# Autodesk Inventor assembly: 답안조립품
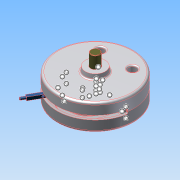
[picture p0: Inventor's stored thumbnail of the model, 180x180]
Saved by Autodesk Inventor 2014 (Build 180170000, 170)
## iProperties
Created: 2015-06
Part Number: 답안조립품
Document SubType Name: Assembly
Designer: Administrator
Author: Administrator
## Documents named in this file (10)
- C:\Documents and Settings\Administrator\바탕 화면\450631V1026\답안조립품.iam
- C:\Documents and Settings\Administrator\바탕 화면\450631V1026\1-본체.ipt
- C:\Documents and Settings\Administrator\바탕 화면\450631V1026\베어링62_22.ipt
- C:\Documents and Settings\Administrator\바탕 화면\450631V1026\축.ipt
- C:\Documents and Settings\Administrator\바탕 화면\450631V1026\멈춤링.ipt
- C:\Documents and Settings\Administrator\바탕 화면\450631V1026\슬라이더2.ipt
- C:\Documents and Settings\Administrator\바탕 화면\450631V1026\슬라이더.ipt
- C:\Documents and Settings\Administrator\바탕 화면\450631V1026\평행핀.ipt
- C:\Documents and Settings\Administrator\바탕 화면\450631V1026\덮개.ipt
- C:\Documents and Settings\Administrator\바탕 화면\450631V1026\M10x35.ipt
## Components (8 placed, 5 different names)
1. 1-본체:1
2. KS B 2023 62/22 - 22 x 50 x 14:1 — 플러쉬:6
3. KS B 1336 22 x 1.2:1 — 플러쉬:6
4. KS B 1336 22 x 1.2:2
5. KS B 1320 B B 5 x  20:1
6. KS B 2023 62/22 - 22 x 50 x 14:2
7. KS B 1003 - 미터 M 10 x 35:1
8. KS B 1003 - 미터 M 10 x 35:2
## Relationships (1: Flush 1)
- 플러쉬:6 [Flush]: KS B 2023 62/22 - 22 x 50 x 14:1 ↔ KS B 1336 22 x 1.2:1
